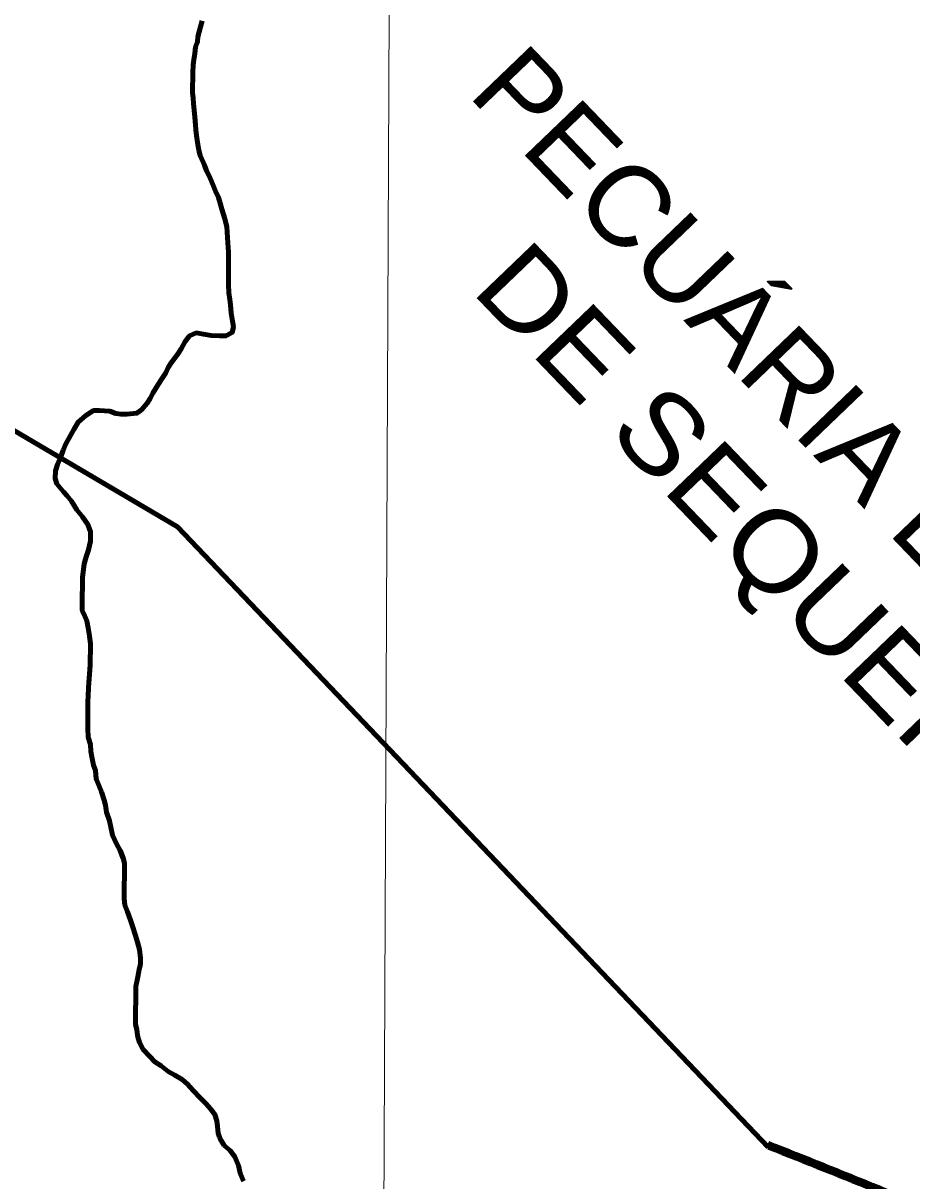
# Model space of a CAD drawing. Extents: x -1643653 to 4543381, y 1624270 to 13878484.
# Drawn here: x 661208 to 669530, y 8933613 to 8944454 of the extents above; entities that cross this region are included whole.
import ezdxf
from ezdxf.enums import TextEntityAlignment as Align

# ---------------------------------------------------------------- set-up
doc = ezdxf.new("R2010")
doc.units = 0
doc.header["$LTSCALE"] = 200
for name, color, linetype, lineweight in [('1', 7, 'Continuous', 13), ('24', 7, 'Continuous', 25), ('26', 7, 'Continuous', 106), ('28', 7, 'Continuous', 53), ('53', 7, 'Continuous', 106), ('60', 7, 'Continuous', 13), ('9', 7, 'Continuous', 90)]:
    doc.layers.add(name, color=color, linetype=linetype, lineweight=lineweight)
doc.layers.add('42', color=7, linetype='Continuous')

msp = doc.modelspace()

# ---------------------------------------------------------------- linework, layer by layer
at = {"layer": '1'}
msp.add_lwpolyline([(664968.2, 9023436.8), (664657.1, 8949509), (664397.1, 8890880.2)], dxfattribs=at)
at = {"layer": '24'}
for points in [[(662794.6, 8943803), (662795.5, 8943990.7), (662800.8, 8944060.7), (662806.1, 8944113.2), (662816.3, 8944165.7), (662821.6, 8944230.7), (662841.9, 8944278.1), (662844.6, 8944325.7), (662867.6, 8944418.1), (662885.3, 8944475.6)], [(661583.1, 8940454), (661608.4, 8940513.9), (661636.2, 8940563.8), (661684.1, 8940648.6), (661724.5, 8940718.5), (661794.8, 8940780.7), (661867.6, 8940825.3), (661920.1, 8940827.6), (662020.2, 8940819.5), (662075.1, 8940799.2), (662125.1, 8940791.5), (662180.2, 8940791.2), (662272.8, 8940800.7), (662315.5, 8940833), (662370.8, 8940895.3), (662396.1, 8940937.7), (662421.3, 8940990.1), (662471.7, 8941069.9), (662507, 8941122.3), (662544.8, 8941179.6), (662565, 8941229.6), (662595.3, 8941274.4), (662625.5, 8941314.3), (662660.7, 8941361.7), (662688.5, 8941404.1), (662726.3, 8941473.9), (662766.6, 8941526.3), (662829.3, 8941553.5), (662896.8, 8941540.6), (662969.3, 8941530.2), (663049.3, 8941524.8), (663106.8, 8941524.5), (663166.2, 8941557.2), (663177.3, 8941611.7), (663167.5, 8941661.8), (663155.4, 8941736.9), (663148.2, 8941817.1), (663143.5, 8941867.1), (663133.7, 8941927.2), (663131.6, 8942007.3), (663129.5, 8942092.4), (663130.5, 8942310.1), (663123.4, 8942397.7), (663121.1, 8942447.7), (663116.6, 8942545.3), (663096.9, 8942623), (663069.8, 8942713.2), (663052.6, 8942768.3), (663037.8, 8942820.9), (663008.1, 8942881.2), (662990.8, 8942928.8), (662953.6, 8943019.1), (662923.9, 8943071.8), (662906.6, 8943124.4), (662864.5, 8943214.7), (662854.7, 8943264.8), (662840, 8943334.9), (662830.3, 8943402.5), (662825.6, 8943455.1), (662820.8, 8943502.6), (662816.1, 8943572.7), (662808.9, 8943637.8), (662804.2, 8943700.4), (662799.4, 8943750.4), (662794.6, 8943803)], [(661761.8, 8939000.7), (661762.8, 8939267), (661773.1, 8939337), (661780.9, 8939392), (661798.7, 8939457), (661821.5, 8939521.9), (661839.4, 8939601.9), (661839.8, 8939689.5), (661812.6, 8939759.7), (661762.9, 8939832.5), (661710.7, 8939897.8), (661661, 8939978.2), (661621.2, 8940028.4), (661586.3, 8940063.6), (661524.1, 8940141.5), (661506.8, 8940189.1), (661509.7, 8940261.7), (661530, 8940321.6), (661565.4, 8940401.5), (661583.1, 8940454)], [(661940.2, 8937257.2), (661921.3, 8937309.4), (661891.6, 8937377.1), (661884.5, 8937454.7), (661867.2, 8937504.8), (661850, 8937585), (661842.8, 8937635.1), (661838.1, 8937700.2), (661818.4, 8937767.8), (661813.7, 8937847.9), (661814.9, 8938103.2), (661817.6, 8938150.7), (661820.5, 8938228.3), (661823.2, 8938275.8), (661828.6, 8938358.3), (661836.5, 8938440.9), (661837.4, 8938638.6), (661830.3, 8938716.2), (661815.6, 8938791.3), (661803.4, 8938856.4), (661786.1, 8938901.6), (661761.3, 8938954.2), (661761.8, 8939000.7)], [(662269, 8935879), (662260.1, 8935911.3), (662230.5, 8935996.6), (662213.3, 8936054.2), (662186.1, 8936131.9), (662158.9, 8936194.6), (662154.1, 8936254.7), (662155.7, 8936587.5), (662143.4, 8936635.1), (662116.2, 8936705.3), (662081.5, 8936768.1), (662044.3, 8936850.8), (662029.6, 8936926), (662017.4, 8936983.6), (661987.8, 8937066.3), (661980.6, 8937131.4), (661965.8, 8937179), (661940.2, 8937257.2)], [(662278.1, 8934978.8), (662271.1, 8935027.9), (662261.3, 8935080.5), (662262.9, 8935433.3), (662280.9, 8935523.3), (662293.7, 8935590.8), (662306.4, 8935643.3), (662306.7, 8935698.4), (662297.1, 8935778.5), (662277.4, 8935848.7), (662269, 8935879)], [(663047.1, 8934021.1), (663034.8, 8934060.5), (663027.5, 8934120.6), (663020.3, 8934175.7), (663003, 8934235.8), (662963.2, 8934288.6), (662920.9, 8934333.8), (662866.1, 8934389.2), (662801.4, 8934459.6), (662746.6, 8934519.9), (662696.8, 8934562.7), (662626.9, 8934603.1), (662567, 8934636), (662499.7, 8934688.9), (662439.8, 8934726.7), (662390, 8934779.5), (662332.8, 8934842.4), (662298, 8934907.6), (662280.8, 8934960.3), (662278.1, 8934978.8)], [(663089.3, 8933942.6), (663052, 8934005.3), (663047.1, 8934021.1)], [(663272.9, 8933611.3), (663240.7, 8933686.5), (663226, 8933756.7), (663191.4, 8933839.4), (663146.6, 8933897.2), (663089.3, 8933942.6)]]:
    msp.add_lwpolyline(points, dxfattribs=at)
at = {"layer": '26'}
for points in [[(645793.1, 8949290.9), (653495.4, 8947850), (659002.1, 8941889), (662654, 8939737.7), (668185.2, 8933928.8)], [(661559, 8940382.7), (662654, 8939737.7), (668185.2, 8933928.8)]]:
    msp.add_lwpolyline(points, dxfattribs=at)
msp.add_spline([(668185.2, 8933965.5), (670277.1, 8933094.3), (672981.1, 8931999.5), (676061.1, 8931869.5), (681079.4, 8933269.5), (681670, 8933656.4)], degree=3, dxfattribs=at)
at = {"layer": '28'}
msp.add_line((661583.1, 8940454), (661559, 8940382.7), dxfattribs=at)
for points in [[(645793.1, 8949290.9), (653495.4, 8947850), (659002.1, 8941889), (661559, 8940382.7), (661583.1, 8940454)], [(662885.3, 8944475.6), (662867.6, 8944418.1), (662844.6, 8944325.7), (662841.9, 8944278.1), (662821.6, 8944230.7), (662816.3, 8944165.7), (662806.1, 8944113.2), (662800.8, 8944060.7), (662795.5, 8943990.7), (662794.6, 8943803)], [(662794.6, 8943803), (662795.5, 8943990.7), (662800.8, 8944060.7), (662806.1, 8944113.2), (662816.3, 8944165.7), (662821.6, 8944230.7), (662841.9, 8944278.1), (662844.6, 8944325.7), (662867.6, 8944418.1), (662885.3, 8944475.6)], [(662794.6, 8943803), (662799.4, 8943750.4), (662804.2, 8943700.4), (662808.9, 8943637.8), (662816.1, 8943572.7), (662820.8, 8943502.6), (662825.6, 8943455.1), (662830.3, 8943402.5), (662840, 8943334.9), (662854.7, 8943264.8), (662864.5, 8943214.7), (662906.6, 8943124.4), (662923.9, 8943071.8), (662953.6, 8943019.1), (662990.8, 8942928.8), (663008.1, 8942881.2), (663037.8, 8942820.9), (663052.6, 8942768.3), (663069.8, 8942713.2), (663096.9, 8942623), (663116.6, 8942545.3), (663121.1, 8942447.7), (663123.4, 8942397.7), (663130.5, 8942310.1), (663129.5, 8942092.4), (663131.6, 8942007.3), (663133.7, 8941927.2), (663143.5, 8941867.1), (663148.2, 8941817.1), (663155.4, 8941736.9), (663167.5, 8941661.8), (663177.3, 8941611.7), (663166.2, 8941557.2), (663106.8, 8941524.5), (663049.3, 8941524.8), (662969.3, 8941530.2), (662896.8, 8941540.6), (662829.3, 8941553.5), (662766.6, 8941526.3), (662726.3, 8941473.9), (662688.5, 8941404.1), (662660.7, 8941361.7), (662625.5, 8941314.3), (662595.3, 8941274.4), (662565, 8941229.6), (662544.8, 8941179.6), (662507, 8941122.3), (662471.7, 8941069.9), (662421.3, 8940990.1), (662396.1, 8940937.7), (662370.8, 8940895.3), (662315.5, 8940833), (662272.8, 8940800.7), (662180.2, 8940791.2), (662125.1, 8940791.5), (662075.1, 8940799.2), (662020.2, 8940819.5), (661920.1, 8940827.6), (661867.6, 8940825.3), (661794.8, 8940780.7), (661724.5, 8940718.5), (661684.1, 8940648.6), (661636.2, 8940563.8), (661608.4, 8940513.9), (661583.1, 8940454)], [(661583.1, 8940454), (661608.4, 8940513.9), (661636.2, 8940563.8), (661684.1, 8940648.6), (661724.5, 8940718.5), (661794.8, 8940780.7), (661867.6, 8940825.3), (661920.1, 8940827.6), (662020.2, 8940819.5), (662075.1, 8940799.2), (662125.1, 8940791.5), (662180.2, 8940791.2), (662272.8, 8940800.7), (662315.5, 8940833), (662370.8, 8940895.3), (662396.1, 8940937.7), (662421.3, 8940990.1), (662471.7, 8941069.9), (662507, 8941122.3), (662544.8, 8941179.6), (662565, 8941229.6), (662595.3, 8941274.4), (662625.5, 8941314.3), (662660.7, 8941361.7), (662688.5, 8941404.1), (662726.3, 8941473.9), (662766.6, 8941526.3), (662829.3, 8941553.5), (662896.8, 8941540.6), (662969.3, 8941530.2), (663049.3, 8941524.8), (663106.8, 8941524.5), (663166.2, 8941557.2), (663177.3, 8941611.7), (663167.5, 8941661.8), (663155.4, 8941736.9), (663148.2, 8941817.1), (663143.5, 8941867.1), (663133.7, 8941927.2), (663131.6, 8942007.3), (663129.5, 8942092.4), (663130.5, 8942310.1), (663123.4, 8942397.7), (663121.1, 8942447.7), (663116.6, 8942545.3), (663096.9, 8942623), (663069.8, 8942713.2), (663052.6, 8942768.3), (663037.8, 8942820.9), (663008.1, 8942881.2), (662990.8, 8942928.8), (662953.6, 8943019.1), (662923.9, 8943071.8), (662906.6, 8943124.4), (662864.5, 8943214.7), (662854.7, 8943264.8), (662840, 8943334.9), (662830.3, 8943402.5), (662825.6, 8943455.1), (662820.8, 8943502.6), (662816.1, 8943572.7), (662808.9, 8943637.8), (662804.2, 8943700.4), (662799.4, 8943750.4), (662794.6, 8943803)], [(661559, 8940382.7), (662654, 8939737.7), (668185.2, 8933928.8), (668185.2, 8933965.5)]]:
    msp.add_lwpolyline(points, dxfattribs=at)
msp.add_spline([(668185.2, 8933965.5), (670277.1, 8933094.3), (672981.1, 8931999.5), (676061.1, 8931869.5), (681079.4, 8933269.5), (681670, 8933656.4)], degree=3, dxfattribs=at)
at = {"layer": '53'}
for points in [[(662794.6, 8943803), (662795.5, 8943990.7), (662800.8, 8944060.7), (662806.1, 8944113.2), (662816.3, 8944165.7), (662821.6, 8944230.7), (662841.9, 8944278.1), (662844.6, 8944325.7), (662867.6, 8944418.1), (662885.3, 8944475.6)], [(661583.1, 8940454), (661608.4, 8940513.9), (661636.2, 8940563.8), (661684.1, 8940648.6), (661724.5, 8940718.5), (661794.8, 8940780.7), (661867.6, 8940825.3), (661920.1, 8940827.6), (662020.2, 8940819.5), (662075.1, 8940799.2), (662125.1, 8940791.5), (662180.2, 8940791.2), (662272.8, 8940800.7), (662315.5, 8940833), (662370.8, 8940895.3), (662396.1, 8940937.7), (662421.3, 8940990.1), (662471.7, 8941069.9), (662507, 8941122.3), (662544.8, 8941179.6), (662565, 8941229.6), (662595.3, 8941274.4), (662625.5, 8941314.3), (662660.7, 8941361.7), (662688.5, 8941404.1), (662726.3, 8941473.9), (662766.6, 8941526.3), (662829.3, 8941553.5), (662896.8, 8941540.6), (662969.3, 8941530.2), (663049.3, 8941524.8), (663106.8, 8941524.5), (663166.2, 8941557.2), (663177.3, 8941611.7), (663167.5, 8941661.8), (663155.4, 8941736.9), (663148.2, 8941817.1), (663143.5, 8941867.1), (663133.7, 8941927.2), (663131.6, 8942007.3), (663129.5, 8942092.4), (663130.5, 8942310.1), (663123.4, 8942397.7), (663121.1, 8942447.7), (663116.6, 8942545.3), (663096.9, 8942623), (663069.8, 8942713.2), (663052.6, 8942768.3), (663037.8, 8942820.9), (663008.1, 8942881.2), (662990.8, 8942928.8), (662953.6, 8943019.1), (662923.9, 8943071.8), (662906.6, 8943124.4), (662864.5, 8943214.7), (662854.7, 8943264.8), (662840, 8943334.9), (662830.3, 8943402.5), (662825.6, 8943455.1), (662820.8, 8943502.6), (662816.1, 8943572.7), (662808.9, 8943637.8), (662804.2, 8943700.4), (662799.4, 8943750.4), (662794.6, 8943803)], [(661761.8, 8939000.7), (661762.8, 8939267), (661773.1, 8939337), (661780.9, 8939392), (661798.7, 8939457), (661821.5, 8939521.9), (661839.4, 8939601.9), (661839.8, 8939689.5), (661812.6, 8939759.7), (661762.9, 8939832.5), (661710.7, 8939897.8), (661661, 8939978.2), (661621.2, 8940028.4), (661586.3, 8940063.6), (661524.1, 8940141.5), (661506.8, 8940189.1), (661509.7, 8940261.7), (661530, 8940321.6), (661565.4, 8940401.5), (661583.1, 8940454)], [(661940.2, 8937257.2), (661921.3, 8937309.4), (661891.6, 8937377.1), (661884.5, 8937454.7), (661867.2, 8937504.8), (661850, 8937585), (661842.8, 8937635.1), (661838.1, 8937700.2), (661818.4, 8937767.8), (661813.7, 8937847.9), (661814.9, 8938103.2), (661817.6, 8938150.7), (661820.5, 8938228.3), (661823.2, 8938275.8), (661828.6, 8938358.3), (661836.5, 8938440.9), (661837.4, 8938638.6), (661830.3, 8938716.2), (661815.6, 8938791.3), (661803.4, 8938856.4), (661786.1, 8938901.6), (661761.3, 8938954.2), (661761.8, 8939000.7)], [(662269, 8935879), (662260.1, 8935911.3), (662230.5, 8935996.6), (662213.3, 8936054.2), (662186.1, 8936131.9), (662158.9, 8936194.6), (662154.1, 8936254.7), (662155.7, 8936587.5), (662143.4, 8936635.1), (662116.2, 8936705.3), (662081.5, 8936768.1), (662044.3, 8936850.8), (662029.6, 8936926), (662017.4, 8936983.6), (661987.8, 8937066.3), (661980.6, 8937131.4), (661965.8, 8937179), (661940.2, 8937257.2)], [(662278.1, 8934978.8), (662271.1, 8935027.9), (662261.3, 8935080.5), (662262.9, 8935433.3), (662280.9, 8935523.3), (662293.7, 8935590.8), (662306.4, 8935643.3), (662306.7, 8935698.4), (662297.1, 8935778.5), (662277.4, 8935848.7), (662269, 8935879)], [(663047.1, 8934021.1), (663034.8, 8934060.5), (663027.5, 8934120.6), (663020.3, 8934175.7), (663003, 8934235.8), (662963.2, 8934288.6), (662920.9, 8934333.8), (662866.1, 8934389.2), (662801.4, 8934459.6), (662746.6, 8934519.9), (662696.8, 8934562.7), (662626.9, 8934603.1), (662567, 8934636), (662499.7, 8934688.9), (662439.8, 8934726.7), (662390, 8934779.5), (662332.8, 8934842.4), (662298, 8934907.6), (662280.8, 8934960.3), (662278.1, 8934978.8)], [(663089.3, 8933942.6), (663052, 8934005.3), (663047.1, 8934021.1)], [(663272.9, 8933611.3), (663240.7, 8933686.5), (663226, 8933756.7), (663191.4, 8933839.4), (663146.6, 8933897.2), (663089.3, 8933942.6)]]:
    msp.add_lwpolyline(points, dxfattribs=at)
at = {"layer": '60', "lineweight": 25}
msp.add_spline([(814781, 9009175.5), (814787.2, 9009173.4), (814796.9, 9009173.4), (814799.4, 9009172.4), (814805.1, 9009174.5), (814805.6, 9009176.5), (814811.7, 9009179.5), (814811.7, 9009179.5), (814801.5, 9009181), (814790.7, 9009181.5), (814784.1, 9009183.1), (814777.4, 9009185.1), (814778.4, 9009175.5)], degree=3, dxfattribs=at)
at = {"layer": '9'}
msp.add_lwpolyline([(645793.1, 8949290.9), (653495.4, 8947850), (659002.1, 8941889), (662654, 8939737.7), (668185.2, 8933928.8)], dxfattribs=at)
for points in [[(637260.6, 8972975.8), (641524.5, 8971056.2), (652526.1, 8965412.7), (653164.3, 8965062.8), (670790.5, 8953770.1), (686194, 8943929.9), (696283.3, 8937647.1)], [(668185.2, 8933928.8), (670277.1, 8933057.6), (672981.1, 8931962.8), (676061.1, 8931832.8), (679695.5, 8932618), (681670, 8933656.4)]]:
    msp.add_spline(points, degree=3, dxfattribs=at)

# ---------------------------------------------------------------- texts
at = {"layer": '42'}
for s, width, p in [('PECUÁRIA LEITEIRA', 1.05, (668947.2, 8940047.1)), ('DE SEQUEIRO', 1.1, (668045.6, 8939181.4))]:
    msp.add_text(s, height=750, rotation=313.835, dxfattribs=dict(at, width=width)).set_placement(p, align=Align.CENTER)

doc.saveas('drawing.dxf')
